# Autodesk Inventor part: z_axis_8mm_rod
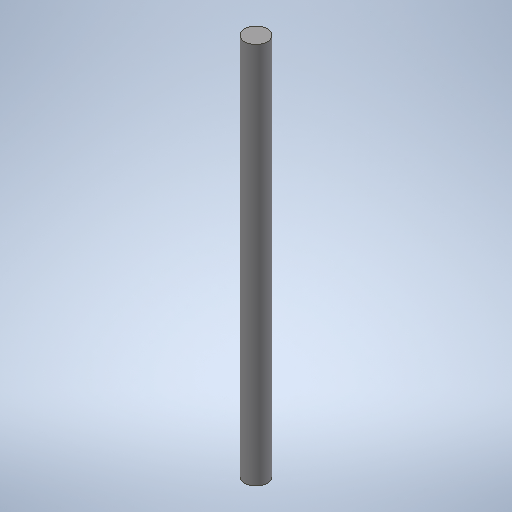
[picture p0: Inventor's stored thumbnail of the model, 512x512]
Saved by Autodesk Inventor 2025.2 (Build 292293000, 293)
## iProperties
Created: 2025-04
Part Number: z_axis_8mm_rod
Material: 1.0037 S235JR
Document SubType Name: Modeling
Designer: BennF
Density: 7.85 g/cm^3
Appearance: Stahl
Author: BennF
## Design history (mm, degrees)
sketch "Sketch2"
  geometry: C1 r 4 at (0, 0); 1 further point
  constraints: 1 centre point, 1 coincident
  dimensions: "d0" = 8 diameter of C1
extrude "Extrusion1" new body sketch "Sketch2" distance "d1" = 135; taper "d2" = 0 deg
body "Solid1"
